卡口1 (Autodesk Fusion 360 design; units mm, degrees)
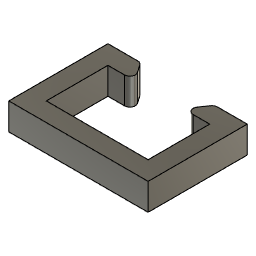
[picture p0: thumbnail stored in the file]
sketch "草图1" plane through (0, 0, 0) normal (0, 0, 1) x axis (1, 0, 0)
  line L1 (13, 9.25) -> (-13, 9.25)
  line L2 (13, -9.25) -> (13, 9.25)
  line L3 (-13, -9.25) -> (13, -9.25)
  line L4 (-13, 9.25) -> (-13, -9.25)
  line L5 (13, -9.25) -> (-13, 9.25)
  line L6 (-13, -9.25) -> (13, 9.25)
  line L7 (9.5, 5.75) -> (-9.5, 5.75)
  line L8 (9.5, -5.75) -> (9.5, 5.75)
  line L9 (-9.5, -5.75) -> (9.5, -5.75)
  line L10 (-9.5, 5.75) -> (-9.5, -5.75)
  line L11 (9.5, -5.75) -> (-9.5, 5.75)
  line L12 (-9.5, -5.75) -> (9.5, 5.75)
  point P6 (0, 0)
  point P1 (0, 0)
  point P11 (0, 0)
  point P4 (13, -9.25)
  point P5 (-13, -9.25)
  horizontal L1
  perpendicular L1 L2
  parallel L1 L3
  parallel L2 L4
  coincident L5 P6
  coincident L6 P6
  coincident P1 P6
  horizontal L7
  perpendicular L7 L8
  parallel L7 L9
  parallel L8 L10
  coincident L11 P11
  coincident L12 P11
  coincident P1 P11
  dimension "d1" distance P4 P5 = 26
  dimension "d2" distance L1 L3 = 18.5
  dimension "d3" distance L8 L10 = 19
  dimension "d4" distance L7 L9 = 11.5
extrude "拉伸1" new body sketch "草图1" profile of L1 L2 L3 L4 L7 L8 L9 L10 along normal blind 5
sketch "草图2" plane through (0, 0, 5) normal (0, 0, 1) x axis (-1, 0, 0)
  line L1 (9.5, 5.75) -> (-9.5, 5.75)
  line L2 (9.5, -5.75) -> (9.5, 5.75)
  line L3 (-9.5, -5.75) -> (9.5, -5.75)
  line L4 (-9.5, 5.75) -> (-9.5, -5.75)
  line L5 (-13, 9.25) -> (13, 9.25)
  line L6 (-13, -9.25) -> (-13, 9.25)
  line L7 (13, -9.25) -> (-13, -9.25)
  line L8 (13, 9.25) -> (13, -9.25)
  line L9 (-6.8986, -9.25) -> (-4.5, -5.75)
  line L10 (6.8986, -9.25) -> (4.5, -5.75)
  point P10 (-4.5, -5.75)
  point P11 (-6.8986, -9.25)
  coincident L3 P10
  coincident L7 P11
  dimension "d7" distance L4 P10 = 5
extrude "拉伸2" cut sketch "草图2" profile of L3 L7 L9 against normal blind 6
fillet "圆角" radius 1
